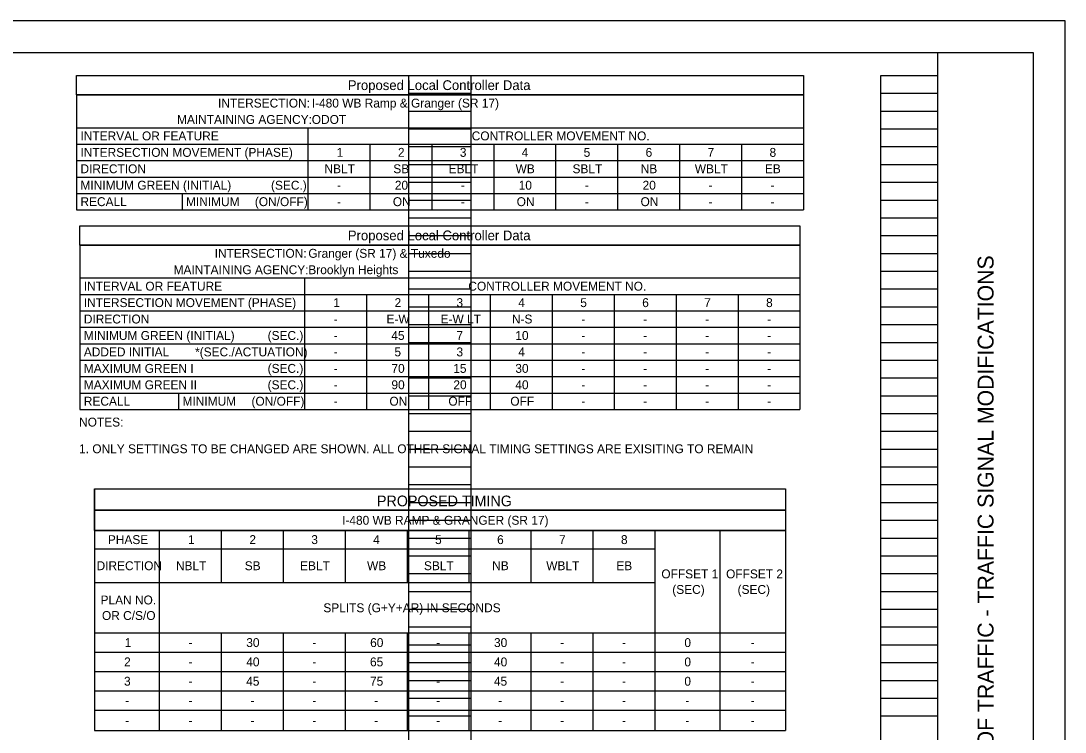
# Model space of a CAD drawing. Extents: x -18.6 to 78.7, y 0 to 36.9.
# Drawn here: x 17.58 to 34, y 10.8 to 22 of the extents above; entities that cross this region are included whole.
import ezdxf

# ---------------------------------------------------------------- set-up
doc = ezdxf.new("R2010")
doc.units = 0
for name, color, linetype in [('Default', 7, 'Continuous'), ('SH_Border', 7, 'Continuous'), ('SH_Cut_Line', 7, 'Continuous'), ('SH_Data', 7, 'Continuous'), ('SH_Text', 7, 'Continuous')]:
    doc.layers.add(name, color=color, linetype=linetype)

msp = doc.modelspace()

# ---------------------------------------------------------------- linework, layer by layer
at = {"layer": 'Default'}
for p, q in [((18.456, 20.836), (29.884, 20.836)), ((18.456, 20.836), (18.456, 19.025)), ((29.884, 20.836), (29.884, 19.025)), ((18.456, 20.318), (29.884, 20.318)), ((22.093, 20.318), (22.093, 19.025)), ((18.456, 20.06), (29.884, 20.06)), ((23.067, 20.06), (23.067, 19.025)), ((24.041, 20.06), (24.041, 19.025)), ((25.015, 20.06), (25.015, 19.025)), ((25.988, 20.06), (25.988, 19.025)), ((26.962, 20.06), (26.962, 19.025)), ((27.936, 20.06), (27.936, 19.025)), ((28.91, 20.06), (28.91, 19.025)), ((18.456, 19.801), (29.884, 19.801)), ((18.456, 19.542), (29.884, 19.542)), ((18.456, 19.284), (29.884, 19.284)), ((20.115, 19.284), (20.115, 19.025)), ((18.456, 19.025), (29.884, 19.025)), ((18.738, 14.634), (29.602, 14.634)), ((18.738, 14.634), (18.738, 10.83)), ((29.602, 14.634), (29.602, 10.83)), ((18.738, 14.299), (29.602, 14.299)), ((18.738, 13.979), (29.602, 13.979)), ((19.757, 13.979), (19.757, 10.83)), ((20.731, 13.979), (20.731, 13.158)), ((21.705, 13.979), (21.705, 13.158)), ((22.679, 13.979), (22.679, 13.158)), ((23.653, 13.979), (23.653, 13.158)), ((24.626, 13.979), (24.626, 13.158)), ((25.6, 13.979), (25.6, 13.158)), ((26.574, 13.979), (26.574, 13.158)), ((27.548, 13.979), (27.548, 10.83)), ((28.568, 13.979), (28.568, 10.83)), ((18.738, 13.69), (27.548, 13.69)), ((18.738, 13.158), (19.757, 13.158)), ((19.757, 13.158), (27.548, 13.158)), ((18.738, 12.366), (29.602, 12.366)), ((20.731, 12.366), (20.731, 10.83)), ((21.705, 12.366), (21.705, 10.83)), ((22.679, 12.366), (22.679, 10.83)), ((23.653, 12.366), (23.653, 10.83)), ((24.626, 12.366), (24.626, 10.83)), ((25.6, 12.366), (25.6, 10.83)), ((26.574, 12.366), (26.574, 10.83)), ((18.738, 12.062), (29.602, 12.062)), ((18.738, 11.758), (29.602, 11.758)), ((18.738, 11.453), (29.602, 11.453)), ((18.738, 11.149), (29.602, 11.149)), ((18.738, 10.83), (29.602, 10.83))]:
    msp.add_line(p, q, dxfattribs=at)
for points in [[(18.456, 21.14), (29.884, 21.14), (29.884, 20.836), (18.456, 20.836)], [(18.738, 14.634), (29.602, 14.634), (29.602, 14.299), (18.738, 14.299)], [(18.738, 14.299), (29.602, 14.299), (29.602, 13.979), (18.738, 13.979)]]:
    msp.add_lwpolyline(points, close=True, dxfattribs=at)
at = {"layer": 'SH_Border'}
msp.add_line((32, 0.5), (32, 21.5), dxfattribs=at)
msp.add_lwpolyline([(1.5, 21.5), (33.5, 21.5), (33.5, 0.5), (1.5, 0.5)], close=True, dxfattribs=at)
at = {"layer": 'SH_Cut_Line'}
msp.add_lwpolyline([(0, 0), (34, 0), (34, 22), (0, 22)], close=True, dxfattribs=at)
at = {"layer": 'SH_Data'}
for p, q in [((23.68, 0.98), (23.68, 21.14)), ((23.68, 21.14), (24.66, 21.14)), ((24.66, 0.98), (24.66, 21.14)), ((31.1, 0.98), (31.1, 21.14)), ((31.1, 21.14), (32, 21.14)), ((32, 0.98), (32, 21.14)), ((23.68, 20.86), (24.66, 20.86)), ((31.1, 20.86), (32, 20.86)), ((23.68, 20.58), (24.66, 20.58)), ((31.1, 20.58), (32, 20.58)), ((23.68, 20.3), (24.66, 20.3)), ((31.1, 20.3), (32, 20.3)), ((23.68, 20.02), (24.66, 20.02)), ((31.1, 20.02), (32, 20.02)), ((23.68, 19.74), (24.66, 19.74)), ((31.1, 19.74), (32, 19.74)), ((23.68, 19.46), (24.66, 19.46)), ((31.1, 19.46), (32, 19.46)), ((23.68, 19.18), (24.66, 19.18)), ((31.1, 19.18), (32, 19.18)), ((23.68, 18.9), (24.66, 18.9)), ((31.1, 18.9), (32, 18.9)), ((23.68, 18.62), (24.66, 18.62)), ((31.1, 18.62), (32, 18.62)), ((23.68, 18.34), (24.66, 18.34)), ((31.1, 18.34), (32, 18.34)), ((23.68, 18.06), (24.66, 18.06)), ((31.1, 18.06), (32, 18.06)), ((23.68, 17.78), (24.66, 17.78)), ((31.1, 17.78), (32, 17.78)), ((23.68, 17.5), (24.66, 17.5)), ((31.1, 17.5), (32, 17.5)), ((23.68, 17.22), (24.66, 17.22)), ((31.1, 17.22), (32, 17.22)), ((23.68, 16.94), (24.66, 16.94)), ((31.1, 16.94), (32, 16.94)), ((23.68, 16.66), (24.66, 16.66)), ((31.1, 16.66), (32, 16.66)), ((23.68, 16.38), (24.66, 16.38)), ((31.1, 16.38), (32, 16.38)), ((23.68, 16.1), (24.66, 16.1)), ((31.1, 16.1), (32, 16.1)), ((23.68, 15.82), (24.66, 15.82)), ((31.1, 15.82), (32, 15.82)), ((23.68, 15.54), (24.66, 15.54)), ((31.1, 15.54), (32, 15.54)), ((23.68, 15.26), (24.66, 15.26)), ((31.1, 15.26), (32, 15.26)), ((23.68, 14.98), (24.66, 14.98)), ((31.1, 14.98), (32, 14.98)), ((23.68, 14.7), (24.66, 14.7)), ((31.1, 14.7), (32, 14.7)), ((23.68, 14.42), (24.66, 14.42)), ((31.1, 14.42), (32, 14.42)), ((23.68, 14.14), (24.66, 14.14)), ((31.1, 14.14), (32, 14.14)), ((23.68, 13.86), (24.66, 13.86)), ((31.1, 13.86), (32, 13.86)), ((23.68, 13.58), (24.66, 13.58)), ((31.1, 13.58), (32, 13.58)), ((23.68, 13.3), (24.66, 13.3)), ((31.1, 13.3), (32, 13.3)), ((23.68, 13.02), (24.66, 13.02)), ((31.1, 13.02), (32, 13.02)), ((23.68, 12.74), (24.66, 12.74)), ((31.1, 12.74), (32, 12.74)), ((23.68, 12.46), (24.66, 12.46)), ((31.1, 12.46), (32, 12.46)), ((23.68, 12.18), (24.66, 12.18)), ((31.1, 12.18), (32, 12.18)), ((23.68, 11.9), (24.66, 11.9)), ((31.1, 11.9), (32, 11.9)), ((23.68, 11.62), (24.66, 11.62)), ((31.1, 11.62), (32, 11.62)), ((23.68, 11.34), (24.66, 11.34)), ((31.1, 11.34), (32, 11.34)), ((23.68, 11.06), (24.66, 11.06)), ((31.1, 11.06), (32, 11.06))]:
    msp.add_line(p, q, dxfattribs=at)
at = {"layer": 'SH_Text'}
for p, q in [((18.509, 18.471), (29.83, 18.471)), ((18.509, 18.471), (18.509, 15.884)), ((29.83, 18.471), (29.83, 15.884)), ((18.509, 17.953), (29.83, 17.953)), ((22.04, 17.953), (22.04, 15.884)), ((18.509, 17.695), (29.83, 17.695)), ((23.013, 17.695), (23.013, 15.884)), ((23.987, 17.695), (23.987, 15.884)), ((24.961, 17.695), (24.961, 15.884)), ((25.935, 17.695), (25.935, 15.884)), ((26.909, 17.695), (26.909, 15.884)), ((27.883, 17.695), (27.883, 15.884)), ((28.857, 17.695), (28.857, 15.884)), ((18.509, 17.436), (29.83, 17.436)), ((18.509, 17.177), (29.83, 17.177)), ((18.509, 16.918), (29.83, 16.918)), ((18.509, 16.66), (29.83, 16.66)), ((18.509, 16.401), (29.83, 16.401)), ((18.509, 16.142), (29.83, 16.142)), ((20.061, 16.142), (20.061, 15.884)), ((18.509, 15.884), (29.83, 15.884))]:
    msp.add_line(p, q, dxfattribs=at)
msp.add_lwpolyline([(18.509, 18.775), (29.83, 18.775), (29.83, 18.471), (18.509, 18.471)], close=True, dxfattribs=at)

# ---------------------------------------------------------------- texts
at = {"layer": 'Default'}
for s, height, p in [('Proposed Local Controller Data', 0.15399, (22.721, 20.911)), ('INTERSECTION:', 0.13999, (20.68, 20.636)), ('I-480 WB Ramp & Granger (SR 17)', 0.13999, (22.154, 20.636)), ('MAINTAINING AGENCY:', 0.13999, (20.035, 20.378)), ('ODOT', 0.14, (22.154, 20.378)), ('INTERVAL OR FEATURE', 0.13999, (18.517, 20.119)), ('CONTROLLER MOVEMENT NO.', 0.13999, (24.669, 20.119)), ('INTERSECTION MOVEMENT (PHASE)', 0.13999, (18.517, 19.86)), ('1', 0.14, (22.545, 19.86)), ('2', 0.14, (23.509, 19.86)), ('3', 0.14, (24.482, 19.86)), ('4', 0.14, (25.455, 19.86)), ('5', 0.14, (26.429, 19.86)), ('6', 0.14, (27.403, 19.86)), ('7', 0.14, (28.378, 19.86)), ('8', 0.14, (29.352, 19.86)), ('DIRECTION', 0.14, (18.517, 19.602)), ('NBLT', 0.14, (22.354, 19.602)), ('SB', 0.14, (23.436, 19.602)), ('EBLT', 0.14, (24.306, 19.602)), ('WB', 0.14, (25.359, 19.602)), ('SBLT', 0.14, (26.254, 19.602)), ('NB', 0.14, (27.326, 19.602)), ('WBLT', 0.14, (28.177, 19.602)), ('EB', 0.14, (29.279, 19.602)), ('MINIMUM GREEN (INITIAL)', 0.13999, (18.517, 19.343)), ('(SEC.)', 0.14, (21.513, 19.343)), ('-', 0.14, (22.551, 19.343)), ('20', 0.14, (23.46, 19.343)), ('-', 0.14, (24.499, 19.343)), ('10', 0.14, (25.408, 19.343)), ('-', 0.14, (26.447, 19.343)), ('20', 0.14, (27.356, 19.343)), ('-', 0.14, (28.394, 19.343)), ('-', 0.14, (29.368, 19.343)), ('RECALL', 0.14, (18.517, 19.084)), ('MINIMUM', 0.14, (20.176, 19.084)), ('(ON/OFF)', 0.14, (21.259, 19.084)), ('ON', 0.14, (23.429, 19.084)), ('ON', 0.14, (25.376, 19.084)), ('ON', 0.14, (27.324, 19.084)), ('-', 0.14, (22.551, 19.084)), ('-', 0.14, (24.499, 19.084)), ('-', 0.14, (26.447, 19.084)), ('-', 0.14, (28.394, 19.084)), ('-', 0.14, (29.368, 19.084)), ('PROPOSED TIMING', 0.16799, (23.179, 14.36)), ('I-480 WB RAMP & GRANGER (SR 17)', 0.13999, (22.631, 14.069)), ('PHASE', 0.14, (18.948, 13.765)), ('1', 0.14, (20.209, 13.765)), ('2', 0.14, (21.173, 13.765)), ('3', 0.14, (22.147, 13.765)), ('4', 0.14, (23.119, 13.765)), ('5', 0.14, (24.093, 13.765)), ('6', 0.14, (25.068, 13.765)), ('7', 0.14, (26.042, 13.765)), ('8', 0.14, (27.016, 13.765)), ('DIRECTION', 0.14, (18.77, 13.354)), ('NBLT', 0.14, (20.018, 13.354)), ('SB', 0.14, (21.1, 13.354)), ('EBLT', 0.14, (21.97, 13.354)), ('WB', 0.14, (23.023, 13.354)), ('SBLT', 0.14, (23.918, 13.354)), ('NB', 0.14, (24.991, 13.354)), ('WBLT', 0.14, (25.841, 13.354)), ('EB', 0.14, (26.943, 13.354)), ('OFFSET 1 ', 0.14, (27.651, 13.225)), ('OFFSET 2 ', 0.14, (28.669, 13.225)), ('(SEC)', 0.14, (27.823, 12.98)), ('(SEC)', 0.14, (28.85, 12.98)), ('PLAN NO. ', 0.14, (18.833, 12.815)), ('SPLITS (G+Y+AR) IN SECONDS', 0.13999, (22.336, 12.692)), ('OR C/S/O', 0.14, (18.855, 12.57)), ('1', 0.14, (19.213, 12.144)), ('-', 0.14, (20.215, 12.144)), ('30', 0.14, (21.124, 12.144)), ('-', 0.14, (22.163, 12.144)), ('60', 0.14, (23.072, 12.144)), ('-', 0.14, (24.111, 12.144)), ('30', 0.14, (25.02, 12.144)), ('-', 0.14, (26.059, 12.144)), ('-', 0.14, (27.032, 12.144)), ('0', 0.14, (28.013, 12.144)), ('-', 0.14, (29.056, 12.144)), ('2', 0.14, (19.203, 11.84)), ('-', 0.14, (20.215, 11.84)), ('40', 0.14, (21.124, 11.84)), ('-', 0.14, (22.163, 11.84)), ('65', 0.14, (23.07, 11.84)), ('-', 0.14, (24.111, 11.84)), ('40', 0.14, (25.02, 11.84)), ('-', 0.14, (26.059, 11.84)), ('-', 0.14, (27.032, 11.84)), ('0', 0.14, (28.013, 11.84)), ('-', 0.14, (29.056, 11.84)), ('3', 0.14, (19.202, 11.536)), ('45', 0.14, (21.123, 11.536)), ('75', 0.14, (23.07, 11.536)), ('45', 0.14, (25.018, 11.536)), ('0', 0.14, (28.013, 11.536)), ('-', 0.14, (20.215, 11.536)), ('-', 0.14, (22.163, 11.536)), ('-', 0.14, (24.111, 11.536)), ('-', 0.14, (26.059, 11.536)), ('-', 0.14, (27.032, 11.536)), ('-', 0.14, (29.056, 11.536)), ('-', 0.14, (19.219, 11.231)), ('-', 0.14, (20.215, 11.231)), ('-', 0.14, (21.189, 11.231)), ('-', 0.14, (22.163, 11.231)), ('-', 0.14, (23.137, 11.231)), ('-', 0.14, (24.111, 11.231)), ('-', 0.14, (25.085, 11.231)), ('-', 0.14, (26.059, 11.231)), ('-', 0.14, (27.032, 11.231)), ('-', 0.14, (28.029, 11.231)), ('-', 0.14, (29.056, 11.231)), ('-', 0.14, (19.219, 10.919)), ('-', 0.14, (20.215, 10.919)), ('-', 0.14, (21.189, 10.919)), ('-', 0.14, (22.163, 10.919)), ('-', 0.14, (23.137, 10.919)), ('-', 0.14, (24.111, 10.919)), ('-', 0.14, (25.085, 10.919)), ('-', 0.14, (26.059, 10.919)), ('-', 0.14, (27.032, 10.919)), ('-', 0.14, (28.029, 10.919)), ('-', 0.14, (29.056, 10.919))]:
    msp.add_text(s, height=height, dxfattribs=at).set_placement(p)
at = {"layer": 'SH_Data'}
msp.add_text('MAINTENANCE OF TRAFFIC - TRAFFIC SIGNAL MODIFICATIONS', height=0.25, rotation=90, dxfattribs=at).set_placement((32.875, 8.038))
at = {"layer": 'SH_Text'}
for s, height, p in [('Proposed Local Controller Data', 0.15399, (22.721, 18.546)), ('INTERSECTION:', 0.13999, (20.627, 18.271)), ('Granger (SR 17) & Tuxedo', 0.13999, (22.1, 18.271)), ('MAINTAINING AGENCY:', 0.13999, (19.981, 18.013)), ('Brooklyn Heights', 0.13999, (22.1, 18.013)), ('INTERVAL OR FEATURE', 0.13999, (18.57, 17.754)), ('CONTROLLER MOVEMENT NO.', 0.13999, (24.616, 17.754)), ('INTERSECTION MOVEMENT (PHASE)', 0.13999, (18.57, 17.495)), ('1', 0.14, (22.492, 17.495)), ('2', 0.14, (23.456, 17.495)), ('3', 0.14, (24.429, 17.495)), ('4', 0.14, (25.401, 17.495)), ('5', 0.14, (26.376, 17.495)), ('6', 0.14, (27.35, 17.495)), ('7', 0.14, (28.325, 17.495)), ('8', 0.14, (29.298, 17.495)), ('DIRECTION', 0.14, (18.57, 17.237)), ('-', 0.14, (22.498, 17.237)), ('E-W', 0.14, (23.329, 17.237)), ('E-W LT', 0.14, (24.18, 17.237)), ('N-S', 0.14, (25.301, 17.237)), ('-', 0.14, (26.393, 17.237)), ('-', 0.14, (27.367, 17.237)), ('-', 0.14, (28.341, 17.237)), ('-', 0.14, (29.315, 17.237)), ('MINIMUM GREEN (INITIAL)', 0.13999, (18.57, 16.978)), ('(SEC.)', 0.14, (21.46, 16.978)), ('45', 0.14, (23.405, 16.978)), ('7', 0.14, (24.429, 16.978)), ('10', 0.14, (25.355, 16.978)), ('-', 0.14, (22.498, 16.978)), ('-', 0.14, (26.393, 16.978)), ('-', 0.14, (27.367, 16.978)), ('-', 0.14, (28.341, 16.978)), ('-', 0.14, (29.315, 16.978)), ('ADDED INITIAL', 0.13999, (18.57, 16.719)), ('*(SEC./ACTUATION)', 0.13999, (20.319, 16.719)), ('-', 0.14, (22.498, 16.719)), ('5', 0.14, (23.454, 16.719)), ('3', 0.14, (24.429, 16.719)), ('4', 0.14, (25.401, 16.719)), ('-', 0.14, (26.393, 16.719)), ('-', 0.14, (27.367, 16.719)), ('-', 0.14, (28.341, 16.719)), ('-', 0.14, (29.315, 16.719)), ('MAXIMUM GREEN I', 0.13999, (18.57, 16.46)), ('(SEC.)', 0.14, (21.46, 16.46)), ('70', 0.14, (23.407, 16.46)), ('15', 0.14, (24.379, 16.46)), ('30', 0.14, (25.355, 16.46)), ('-', 0.14, (22.498, 16.46)), ('-', 0.14, (26.393, 16.46)), ('-', 0.14, (27.367, 16.46)), ('-', 0.14, (28.341, 16.46)), ('-', 0.14, (29.315, 16.46)), ('MAXIMUM GREEN II', 0.13999, (18.57, 16.202)), ('(SEC.)', 0.14, (21.46, 16.202)), ('-', 0.14, (22.498, 16.202)), ('90', 0.14, (23.407, 16.202)), ('20', 0.14, (24.381, 16.202)), ('40', 0.14, (25.355, 16.202)), ('-', 0.14, (26.393, 16.202)), ('-', 0.14, (27.367, 16.202)), ('-', 0.14, (28.341, 16.202)), ('-', 0.14, (29.315, 16.202)), ('RECALL', 0.14, (18.57, 15.943)), ('MINIMUM', 0.14, (20.122, 15.943)), ('(ON/OFF)', 0.14, (21.206, 15.943)), ('-', 0.14, (22.498, 15.943)), ('ON', 0.14, (23.375, 15.943)), ('OFF', 0.14, (24.302, 15.943)), ('OFF', 0.14, (25.276, 15.943)), ('-', 0.14, (26.393, 15.943)), ('-', 0.14, (27.367, 15.943)), ('-', 0.14, (28.341, 15.943)), ('-', 0.14, (29.315, 15.943)), ('NOTES: ', 0.14, (18.495, 15.615)), ('1. ONLY SETTINGS TO BE CHANGED ARE SHOWN. ALL OTHER SIGNAL TIMING SETTINGS ARE EXISITING TO REMAIN', 0.14, (18.495, 15.195))]:
    msp.add_text(s, height=height, dxfattribs=at).set_placement(p)

doc.saveas('drawing.dxf')
